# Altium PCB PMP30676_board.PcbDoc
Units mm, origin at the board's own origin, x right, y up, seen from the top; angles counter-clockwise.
Board outline 63.5 x 50.29 mm, 4 copper layers (Top Layer, GND, Signal Layer, Bottom Layer), stack 2.028 mm thick; 44 components, 21 nets, 103 pads, 77 vias.
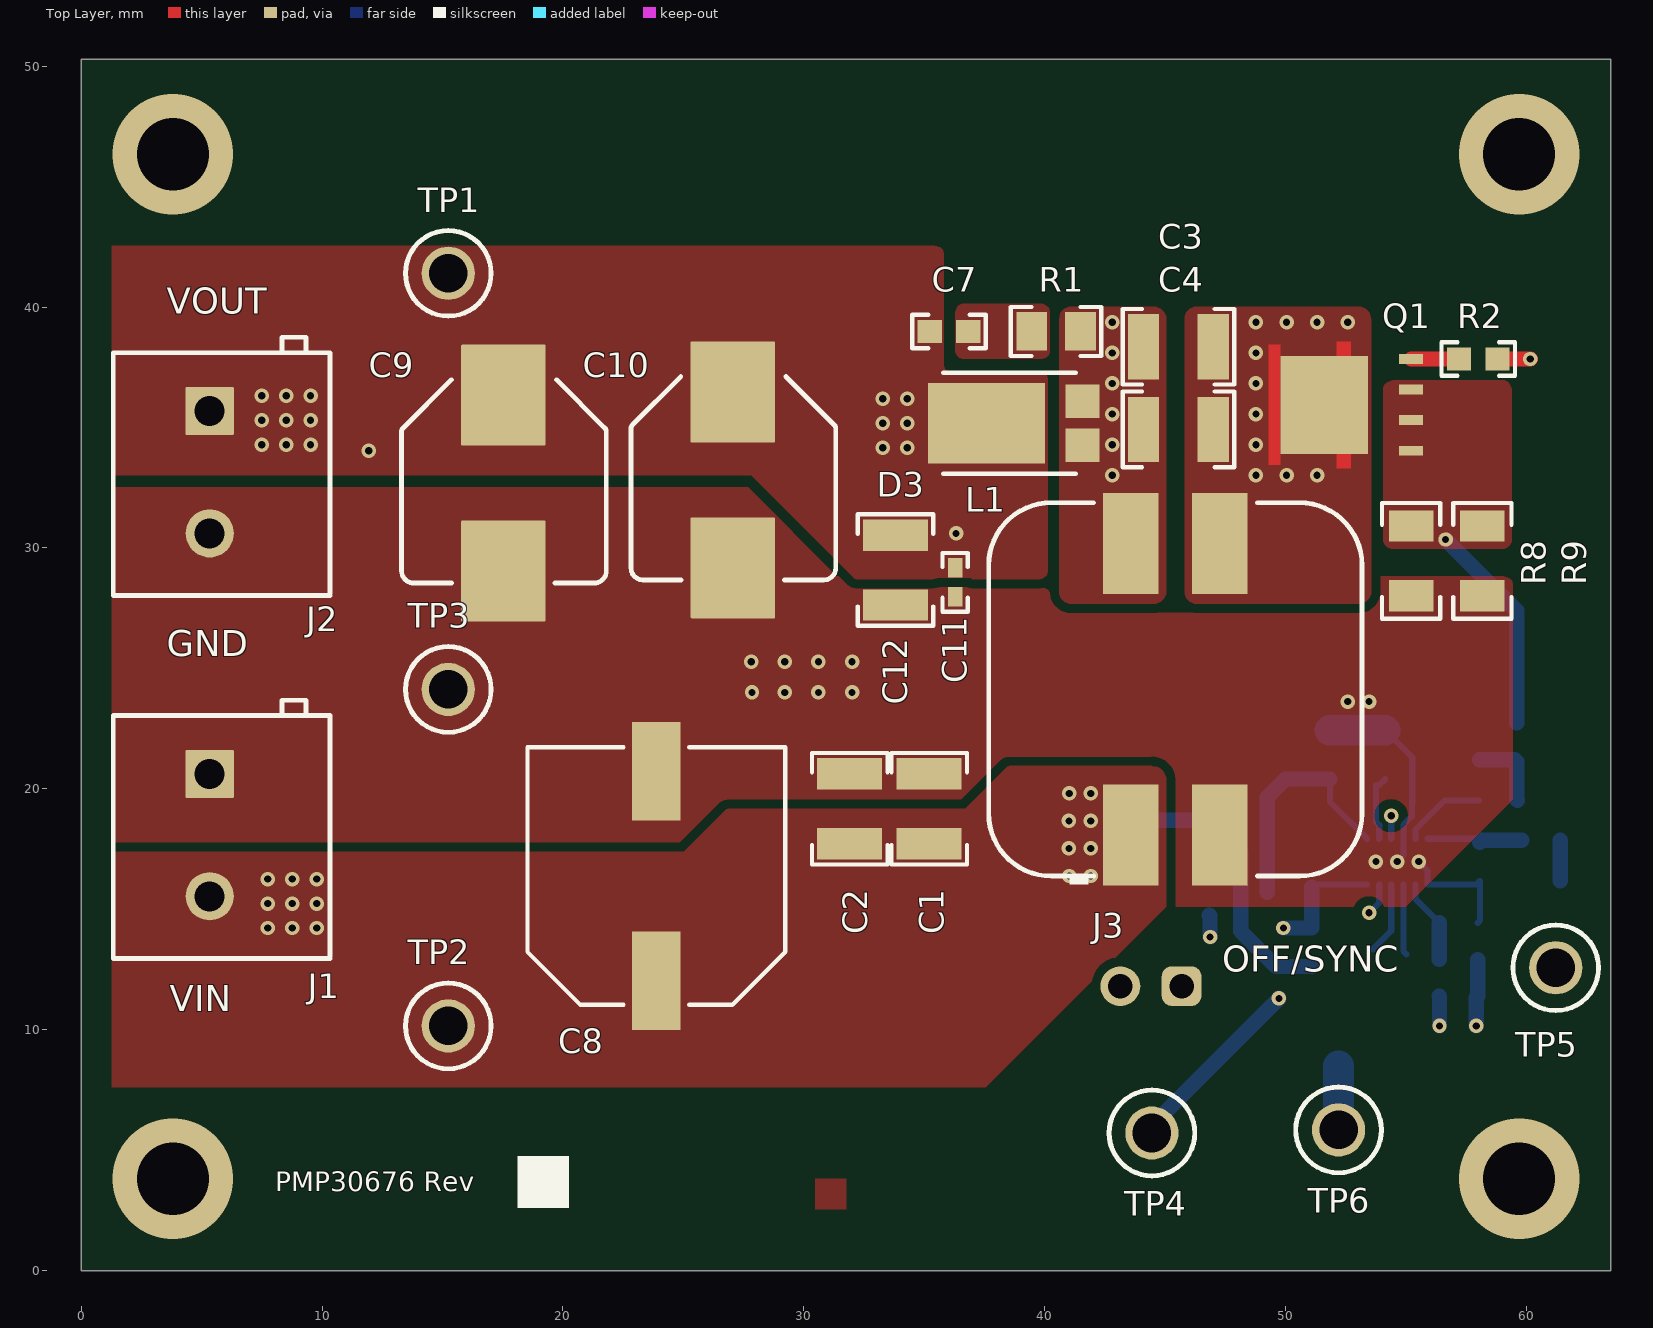
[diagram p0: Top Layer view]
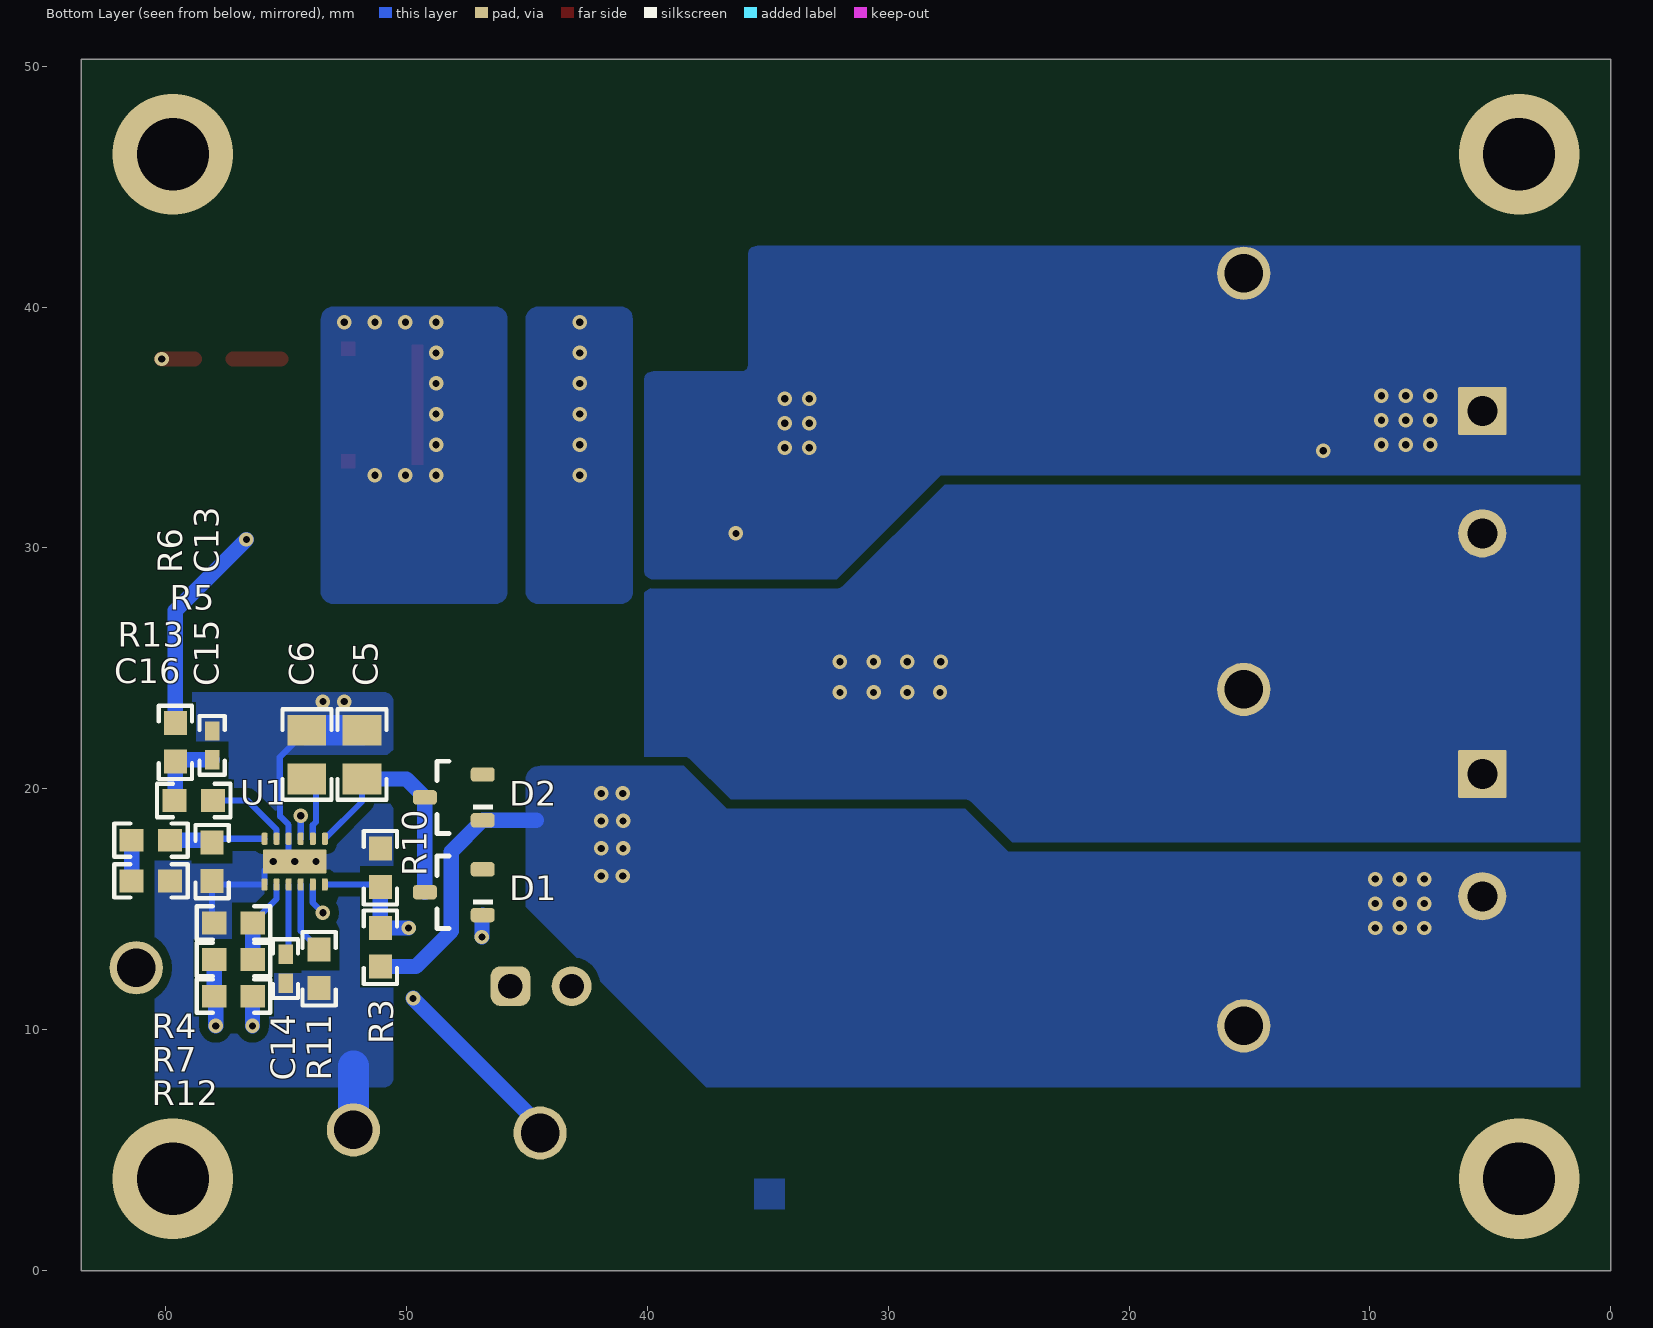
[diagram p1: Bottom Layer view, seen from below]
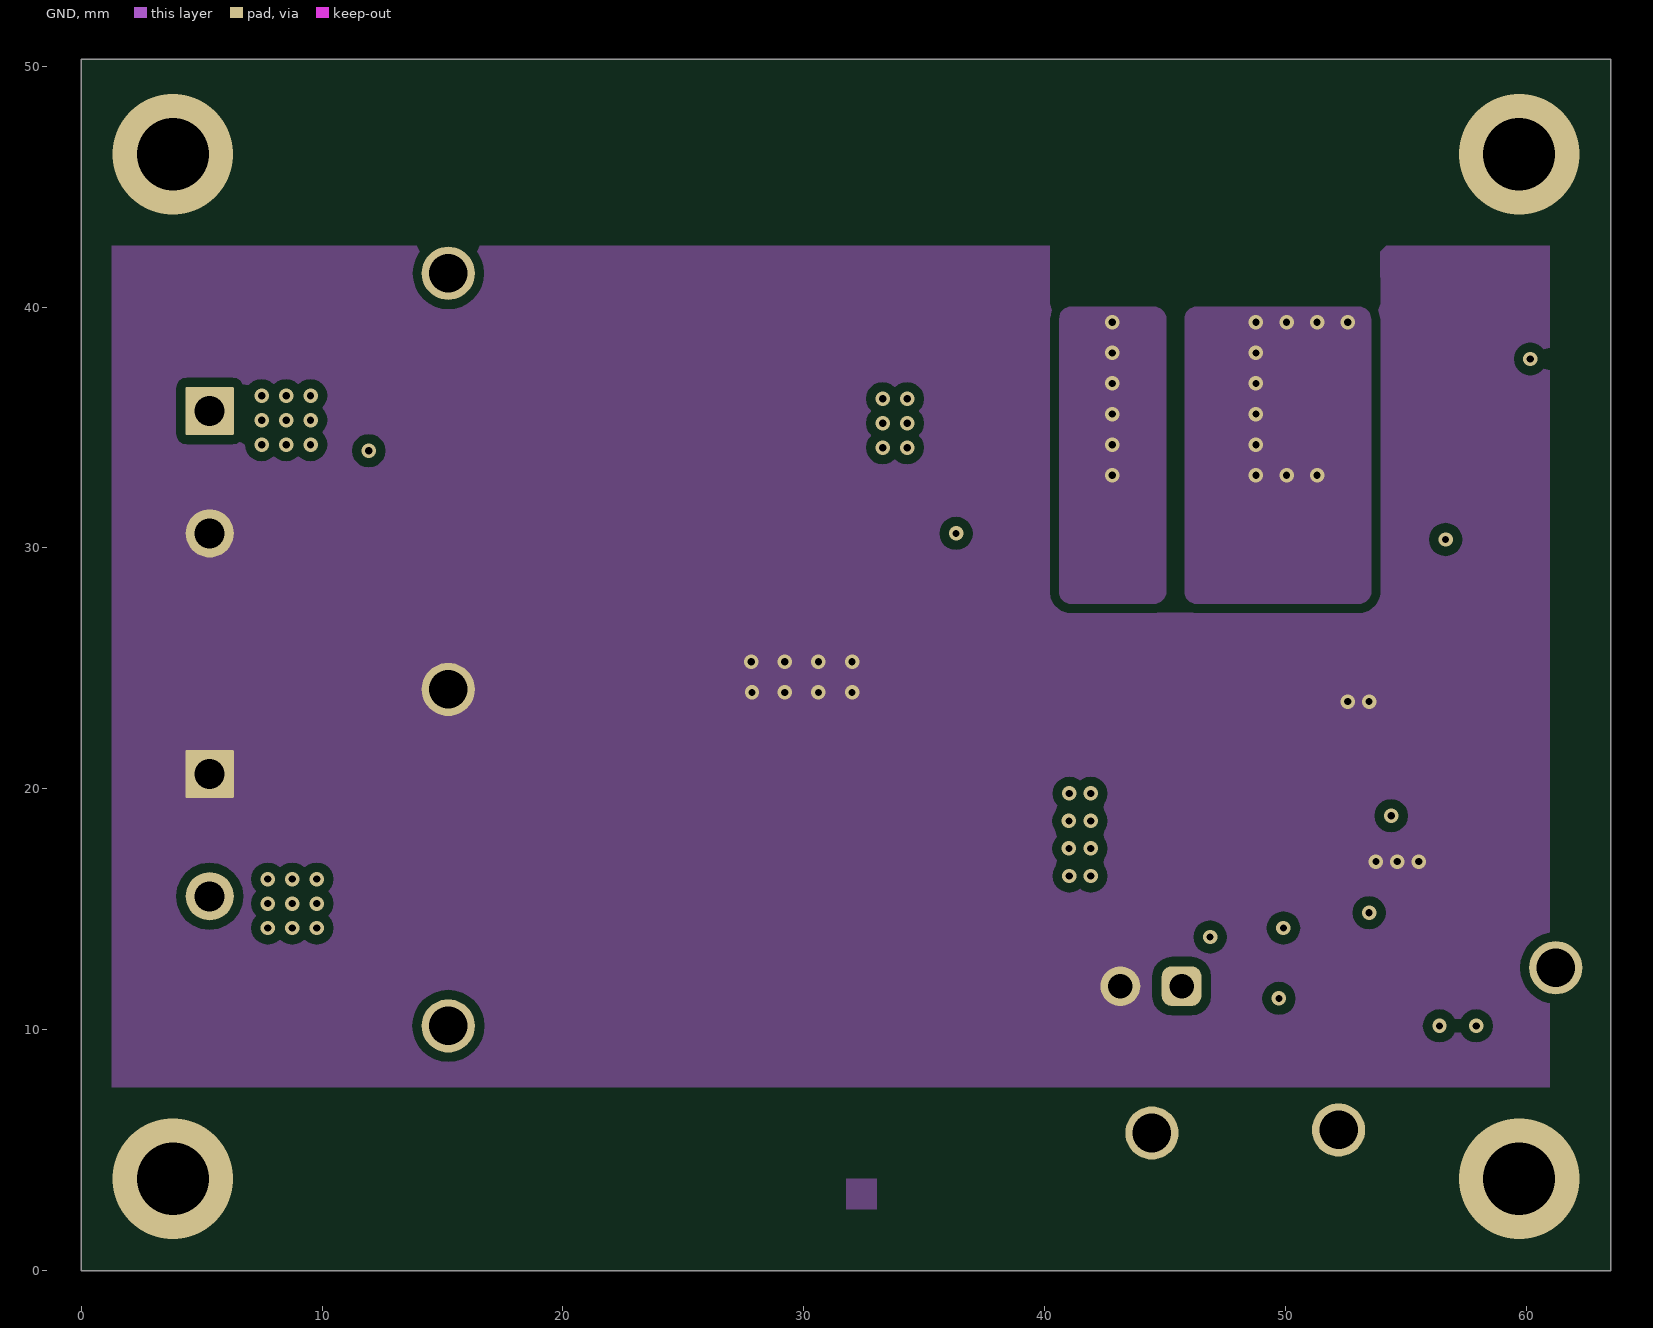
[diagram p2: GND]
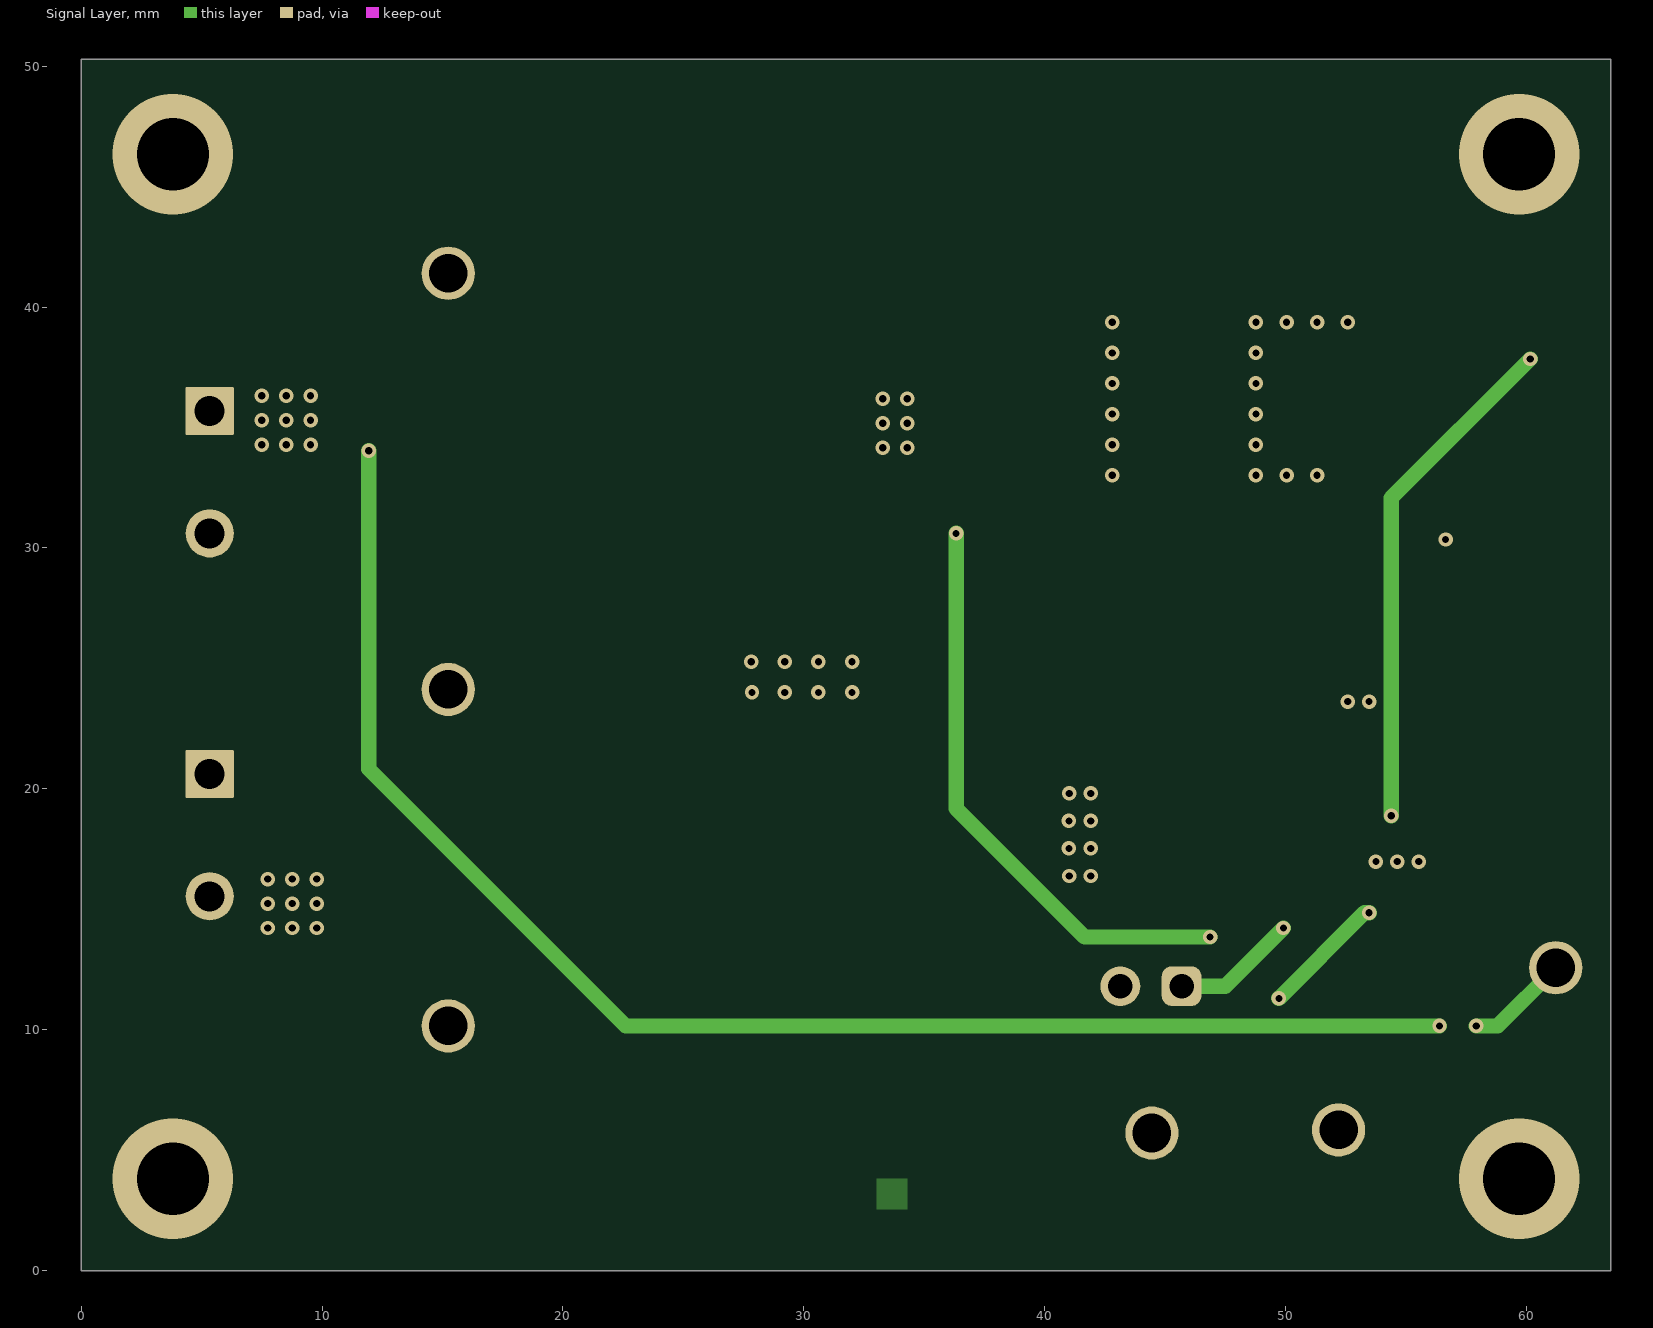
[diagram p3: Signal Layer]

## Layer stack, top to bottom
Top Solder: solder mask 0.0102, Solder Resist, Dk 3.5
Top Layer: signal copper 0.0356
Dielectric1: core 1.5037, FR-4, Dk 4.8
GND: signal copper 0.036
Dielectric 3: prepreg 0.127, Dk 4.2
Signal Layer: signal copper 0.036
Dielectric 2: core 0.254, Dk 4.2
Bottom Layer: signal copper 0.0356
Bottom Solder: solder mask 0.0102, Solder Resist, Dk 3.5

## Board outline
0,0 63.5,0 63.5,50.292 0,50.292

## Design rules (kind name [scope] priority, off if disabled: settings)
AcuteAngle [All] p1: minimum=4.50000000000000E+0001 checktracksonly=FALSE
AssemblyTestPointUsage [All] p1: valid=2
Clearance Clearance_Keepouts [((IsTrack Or IsArc) And Not InPoly) And IsFree and IsKeepOut vs ((IsTrack Or IsArc) And Not InPoly) And IsFree and IsKeepOut] p1: gap=0 ignorepadtopadclearanceinfootprint=FALSE
Clearance Clearance_BoardEdge_MountingHoles [OnCopper and InComponentClass('Mounting Holes') vs IsKeepOut] p2: gap=1.016 ignorepadtopadclearanceinfootprint=FALSE except(0: Arc-Hole Track-Hole SMDPad-Hole THPad-Hole Via-Hole Fill-Hole Poly-Hole Region-Hole Text-Hole)
Clearance Clearance_BoardEdge_Poly [OnCopper and InPoly vs IsKeepOut] p3: gap=0.635 ignorepadtopadclearanceinfootprint=FALSE except(0: Arc-Hole Track-Hole SMDPad-Hole THPad-Hole Via-Hole Fill-Hole Poly-Hole Region-Hole Text-Hole)
Clearance Clearance_BoardEdge [OnCopper and Not InComponentClass('Logo') and not InComponentClass('FiducialMark') and not InRegion(1000,500,4000,800) and Not IsKeepout vs IsKeepOut] p4: gap=1.905 ignorepadtopadclearanceinfootprint=FALSE except(0: Arc-Hole Track-Hole SMDPad-Hole THPad-Hole Via-Hole Fill-Hole Poly-Hole Region-Hole Text-Hole)
Clearance Clearance_Poly [InPolygon] p5: gap=0.381 ignorepadtopadclearanceinfootprint=FALSE except(0: Arc-Hole Track-Hole SMDPad-Hole THPad-Hole Via-Hole Fill-Hole Poly-Hole Region-Hole Text-Hole)
Clearance [All] p6: gap=0.2 ignorepadtopadclearanceinfootprint=FALSE except(0: Arc-Hole Track-Hole SMDPad-Hole THPad-Hole Via-Hole Fill-Hole Poly-Hole Region-Hole Text-Hole)
ComponentClearance ComponentClearance_MountingHoles_FiducialMarks [InComponentClass('Mounting Holes') vs InComponentClass('FiducialMark')] p1: gap=1.27 collisioncheckmode=3 verticalgap=0.254 showdistances=FALSE
ComponentClearance ComponentClearance_Shunt [InComponentClass('Header') vs InComponentClass('Shunt')] p2: gap=0 collisioncheckmode=3 verticalgap=0 showdistances=FALSE
ComponentClearance ComponentClearance_Logo [InComponentClass('Logo')] p3: gap=1.27 collisioncheckmode=3 verticalgap=0.254 showdistances=FALSE
ComponentClearance ComponentClearance_ScrewToNut [(HasFootprint('NY PMS 440 0025 PH')) vs (HasFootprint('Keystone_1902C'))] p4: gap=0.127 collisioncheckmode=3 verticalgap=0.254 showdistances=FALSE
ComponentClearance ComponentClearance_MountingHoles [InComponentClass('Mounting Holes')] p5: gap=6.35 collisioncheckmode=3 verticalgap=2540 showdistances=FALSE
ComponentClearance ComponentClearance_SmallPassives [HasFootprint('0201*') or HasFootprint('0402*') or HasFootprint('0508') or HasFootprint('0603*') or HasFootprint('0612') or HasFootprint('0805*') or HasFootprint('0815*') or HasFootprint('0830*') or HasFootprint('1206*') or HasFootprint('1210*') or HasFootprint('1808*') or HasFootprint('1812*') or HasFootprint('1825*') or HasFootprint('2010*') or HasFootprint('2220*') or HasFootprint('2225*') or HasFootprint('2512*') or HasFootprint('2728*') or HasFootprint('3518*') vs HasFootprint('0201*') or HasFootprint('0402*') or HasFootprint('0508') or HasFootprint('0603*') or HasFootprint('0612') or HasFootprint('0805*') or HasFootprint('0815*') or HasFootprint('0830*') or HasFootprint('1206*') or HasFootprint('1210*') or HasFootprint('1808*') or HasFootprint('1812*') or HasFootprint('1825*') or HasFootprint('2010*') or HasFootprint('2220*') or HasFootprint('2225*') or HasFootprint('2512*') or HasFootprint('2728*') or HasFootprint('3518*')] p6: gap=0.508 collisioncheckmode=3 verticalgap=0.254 showdistances=FALSE
ComponentClearance ComponentClearance_THtoSMT [IsThruComponent vs IsSMTComponent] p7: gap=2.54 collisioncheckmode=3 verticalgap=0.762 showdistances=FALSE
ComponentClearance ComponentClearance_THtoTH [IsThruComponent vs IsThruComponent] p8: gap=3 collisioncheckmode=3 verticalgap=0.762 showdistances=FALSE
ComponentClearance [All] p9: gap=1.016 collisioncheckmode=3 verticalgap=0.254 showdistances=FALSE
DiffPairsRouting [All] p1: maxlimit=2.54 minlimit=0.254 mostfreqgap=0.254 toplayer_minwidth=0.381 toplayer_maxwidth=0.381 toplayer_prefwidth=0.381 midlayer1_minwidth=0.381 midlayer1_maxwidth=0.381 midlayer1_prefwidth=0.381 midlayer2_minwidth=0.381 midlayer2_maxwidth=0.381 midlayer2_prefwidth=0.381 bottomlayer_minwidth=0.381 bottomlayer_maxwidth=0.381 bottomlayer_prefwidth=0.381 maxuncoupledlength=25.4
FabricationTestPointUsage TestPointUsage [All] p1: valid=2 allowmultiple=FALSE
FabricationTestpoint Testpoint [All] p1: side=3 testpointundercomponent=TRUE minsize=1.016 maxsize=2.54 preferedsize=1.524 minholesize=0 maxholesize=1.016 preferedholesize=0.813 testpointgrid=0.025 allowsidetop=TRUE allowsidebottom=TRUE usegrid=TRUE gridtolerance=0
FanoutControl Fanout_LCC [IsLCC] p1: bgadir=Out bgaviamode=Centered fanoutstyle=Auto fanoutdirection=Alternating viagrid=0.025 // Fanout_LCC (Default Rule)
FanoutControl Fanout_BGA [IsBGA] p2: bgadir=Out bgaviamode=Centered fanoutstyle=Auto fanoutdirection=Alternating viagrid=0.025 // Fanout_BGA (Default Rule)
FanoutControl Fanout_Default [All] p4: bgadir=Out bgaviamode=Centered fanoutstyle=Auto fanoutdirection=Alternating viagrid=0.025 // Fanout_Default (Default Rule)
FanoutControl Fanout_Small [(CompPinCount < 5)] p5: bgadir=Out bgaviamode=Centered fanoutstyle=Auto fanoutdirection=OutThenIn viagrid=0.025 // Fanout_Small (Default Rule)
HoleSize [All] p1: absolutevalues=TRUE maxlimit=6.375 minlimit=0.3 maxpercent=80.000 minpercent=20.000
MinimumAnnularRing MinimumAnnularRing_ThermalPadVias [IsVia and InAnyComponent] p1: minimumring=0.15
MinimumAnnularRing [All] p2: minimumring=0.15
MinimumSolderMaskSliver MinimumSolderMaskSliver_Logo [InComponentClass('Logo') vs InComponentClass('Logo')] p1: minsoldermaskwidth=0.018
MinimumSolderMaskSliver [All] p2: minsoldermaskwidth=0.1
PlaneConnect [All] p1: planeconnectstyle=Relief reliefexpansion=0.254 reliefentries=4 reliefconductorwidth=0.254 reliefairgap=0.254
PolygonConnect [All] p1: connectstyle=Direct reliefconductorwidth=0.254 reliefentries=4 polygonreliefangle="90 Angle" airgapwidth=0.254
RoutingVias ThermalPadVias [IsVia and InAnyComponent] p1: holewidth=0.2 width=0.5 viastyle="Through Hole" minholewidth=0.3 minwidth=0.6 maxholewidth=0.33 maxwidth=0.6
RoutingVias [All] p2: holewidth=0.3 width=0.6 viastyle="Through Hole" minholewidth=0.3 minwidth=0.6 maxholewidth=1.016 maxwidth=1.651
SilkToBoardRegionClearance [Not ((IsComment or IsDesignator) And (Hide <> 'False')) and not InRegion(1000,500,4000,800)] p1:
SilkToSilkClearance SilkToSilkClearance_Pb-FreeLogo [(HasFootprint('Pb-Free_Overlay_Medium') OR HasFootprint('Pb-Free_Overlay_Small')) vs (HasFootprint('Pb-Free_Overlay_Medium') OR HasFootprint('Pb-Free_Overlay_Small'))] p1: silktosilkclearance=0
SilkToSilkClearance [All] p2: silktosilkclearance=0.102
SilkToSolderMaskClearance SilkToComonentPadClearance [IsPad and InAnycomponent] p1: minsilkscreentomaskgap=0.127 clearancetoexposedcopper=TRUE
SilkToSolderMaskClearance "Silk to Solder Mask Opening" [All] p2: minsilkscreentomaskgap=0.102 clearancetoexposedcopper=FALSE
SolderMaskExpansion [All] p1: expansion=0.05
Width [All] p1: maxlimit=2.54 minlimit=0.152 preferedwidth=0.254 checkconnectedcopper=TRUE
15 further rules are at their usual default settings.

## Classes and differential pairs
component class Header: J3

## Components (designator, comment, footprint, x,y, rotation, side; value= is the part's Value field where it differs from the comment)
C1 "GRM32ER71H106KA12L" 1210_270 35.205,19.177 r90 top value=10uF
C2 "GRM32ER71H106KA12L" 1210_270 31.903,19.177 r90 top value=10uF
C3 "GRM32ER71H106KA12L" 1210_270 45.55,38.354 r0 top value=10uF
C4 "GRM32ER71H106KA12L" 1210_270 45.55,34.925 r0 top value=10uF
C5 "GRM21BR71H105KA12L" 0805_HV 51.842,21.425 r270 bottom value=1uF
C6 "GRM21BR71A105KA01L" 0805_HV 54.128,21.425 r90 bottom value=1uF
C7 "GRM188R71H102KA01D" 0603 36.025,38.989 r180 top value=1000pF
C8 "EEE-FC1H101P" SM_RADIAL_G 23.876,16.383 r90 top value=100uF
C9 "HHXC250ARA221MHA0G" HXB_HA0 17.526,33.147 r270 top value=220uF
C10 "HHXC250ARA221MHA0G" HXB_HA0 27.051,33.274 r270 top value=220uF
C11 "GRM155R71H104ME14D" 0402 36.279,28.575 r270 top value=0.1uF
C12 "GRM32DR71E106KA12L" 1210_220 33.808,29.083 r270 top value=10uF
C13 "GRM155R61E102KA01D" 0402 58.065,21.806 r90 bottom value=1000pF
C14 "GRM155R71C104KA88D" 0402 55.017,12.535 r270 bottom value=0.1uF
C15 "GRM188R71E332KA01D" 0603 58.065,16.98 r270 bottom value=3300pF
C16 "GRM188R71A334KA61D" 0603 60.605,16.18 r180 bottom value=0.33uF
D1 "BAS16LT1G" SOT-23 48.032,15.71 r0 bottom value=100V
D2 "BAS16LT1G" SOT-23 48.032,19.647 r0 bottom value=100V
D3 "PDS560-13" POWERDI5 39.581,35.179 r180 top value=60V
J1 "ED120/2DS" On-Shore_ED120_2DS 5.334,18.08 r270 top
J2 "ED120/2DS" On-Shore_ED120_2DS 5.334,33.147 r270 top
J3 "TSW-102-07-G-S" TSW-102-07-G-S 44.412,11.811 r180 top
L1 "MSD1514-223MEB" MSD1514 45.423,24.13 r90 top value=22uH
Q1 "SQJA60EP" PowerPAK_SO-8L 52.408,35.941 r180 top value=60V
R1 "CRCW08051R00FKEA" 0805_HV 40.47,38.989 r0 top value=1.00
R2 "ERJ-3GEY0R00V" 0603 57.996,37.846 r180 top value=0
R3 "CRCW0603261KFKEA" 0603 51.08,13.424 r270 bottom value=261k
R4 "CRCW060349R9FKEA" 0603 57.176,11.392 r180 bottom value=49.9
R5 "ERJ-3GEY0R00V" 0603 58.827,19.52 r0 bottom value=0
R6 "CRCW0603100RFKEA" 0603 59.589,21.933 r90 bottom value=100
R7 "CRCW060360K4FKEA" 0603 57.176,12.916 r0 bottom value=60.4k
R8 "CSR1206FK15L0" 1206 55.213,29.464 r90 top value=0.015
R9 "CSR1206FK15L0" 1206 58.166,29.464 r90 top value=0.015
R10 "CRCW060386K6FKEA" 0603 51.08,16.726 r270 bottom value=86.6k
R11 "CRCW060371K5FKEA" 0603 53.62,12.535 r90 bottom value=71.5k
R12 "CRCW06035K49FKEA" 0603 57.176,14.44 r180 bottom value=5.49k
R13 "CRCW06036K49FKEA" 0603 60.605,17.869 r180 bottom value=6.49k
TP1 "5010" Keystone5010 15.24,41.402 r0 top
TP2 "5010" Keystone5010 15.24,10.16 r0 top
TP3 "5011" Keystone5011 15.24,24.13 r0 top
TP4 "5012" Keystone5012 44.45,5.715 r0 top
TP5 "5014" Keystone5014 61.214,12.573 r0 top
TP6 "5011" Keystone5011 52.197,5.842 r0 top
U1 "LM51551QDSSRQ1" DSS0012C 54.636,16.98 r270 bottom

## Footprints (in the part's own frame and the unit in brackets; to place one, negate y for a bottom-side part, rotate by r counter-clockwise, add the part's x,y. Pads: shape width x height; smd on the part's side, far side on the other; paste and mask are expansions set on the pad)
0402 [mm] "0402 from SM-752 data"
  rect 0.8x0.6 smd: 1(-0.6,0) 2(0.6,0)
  silkscreen extent -1.22,-0.52 1.22,0.52, body extent -0.55,-0.3 0.55,0.3, height 0.6
0603 [mm] "0603 from SM-752 data"
  rect 1x0.95 smd: 1(-0.8,0) 2(0.8,0)
  silkscreen extent -1.52,-0.69 1.52,0.69, body extent -0.87,-0.47 0.87,0.47, height 1
0805_HV [mil] "0805 with 30mil clearance between pads"
  rect 50x63 smd: 1(-40,0) 2(40,0)
  silkscreen extent -74,-40 74,40, body extent -43,-29 43,29, height 57
1206 [mm] "1206 from SM-752 data"
  rect 1.3x1.85 smd: 1(-1.45,0) 2(1.45,0)
  silkscreen extent -2.4,-1.21 2.4,1.21, body extent -1.7,-0.9 1.7,0.9, height 1.35
1210_220 [mm] "1210"
  rect 1.3x2.7 smd: 1(-1.45,0) 2(1.45,0)
  silkscreen extent -2.32,-1.57 2.32,1.57, body extent -1.7,-1.35 1.7,1.35, height 2.2
1210_270 [mm] "1210"
  rect 1.3x2.7 smd: 1(-1.45,0) 2(1.45,0)
  silkscreen extent -2.32,-1.57 2.32,1.57, body extent -1.7,-1.35 1.7,1.35, height 2.7
DSS0012C [mm] "WSON-12"
  rrect40% 0.5x0.25 smd: 1(-0.95,1.25) 2(-0.95,0.75) 3(-0.95,0.25) 4(-0.95,-0.25) 5(-0.95,-0.75) 6(-0.95,-1.25) 7(0.95,-1.25) 8(0.95,-0.75) 9(0.95,-0.25) 10(0.95,0.25) 11(0.95,0.75) 12(0.95,1.25)
  rrect11% 0.95x1.17 on Bottom Paste: 13(0,-0.685) 13(0,0.685)
  rrect11% 1x2.65 smd paste-0.5: 13(0,0)
  body extent -1,-1.5 1,1.5, height 0.81
HXB_HA0 [mm] "SMD, 2-Leads, Dia 8mm"
  rrect3% 4.2x3.5 smd: 1(-3.2,0) 2(4.1,0)
  silkscreen extent -3.84,-4.23 4.6,4.28, body extent -4.22,-4.2 4.98,4.3, height 10.5
Keystone5010 [mil] "Keystone Multipurpose loops"
  round 87 hole 63: 1(0,0)
  silkscreen extent -70,-70 70,70, body extent -63,-63 63,62, height 319
Keystone5011 [mil] "Keystone Multipurpose loops"
  round 87 hole 63: 1(0,0)
  silkscreen extent -70,-70 70,70, body extent -63,-63 63,62, height 319
Keystone5012 [mil] "Keystone Multipurpose loops"
  round 87 hole 63: 1(0,0)
  silkscreen extent -70,-70 70,70, body extent -63,-63 63,62, height 319
Keystone5014 [mil] "Keystone Multipurpose loops"
  round 87 hole 63: 1(0,0)
  silkscreen extent -70,-70 70,70, body extent -63,-63 63,62, height 319
MSD1514 [mm] "SMD, 4-Leads, Body 15x15mm"
  rect 4.2x2.3 smd: 1(-6.05,1.85) 2(-6.05,-1.85) 3(6.05,-1.85) 4(6.05,1.85)
  silkscreen extent -8.1,-7.75 7.75,7.75, body extent -7.81,-7.75 7.79,7.75, height 14.2
On-Shore_ED120_2DS [mm] "ONSHORE"
  rrect5% 2x2 hole 1.25: 1(-2.54,0)
  round 2 hole 1.25: 2(2.54,0)
  silkscreen extent -5.6,-4 5.12,5, body extent -5.78,-4 5.08,5, height 13
POWERDI5 [mm] "Diodes Inc recommended land pattern, ap02001.pdf rev 60"
  rect 1.4x1.39 smd: 1(-1.991,0.92) 2(-1.991,-0.92)
  rect 4.86x3.36 smd: 3(1.991,0)
  silkscreen extent -1.7,-2.1 3.8,2.1, body extent -2.27,-2.03 4.33,2.03, height 1.17
PowerPAK_SO-8L [mm] "based on Vishay recommended land pattern Document 63818 Feb 7, 2012"
  rect 1x0.41 smd: 1(-2.805,1.905) 2(-2.805,0.635) 3(-2.805,-0.635) 4(-2.805,-1.905)
  rect 3.63x4.061 smd: 5(0.805,0)
  Top Layer region: 2.615,-2.5 3.125,-2.5 3.125,2.5 2.615,2.5
  Top Layer region: -0.298,2.03 0.297,2.03 0.297,2.64 -0.298,2.64
  Top Layer region: -0.298,-2.64 0.298,-2.64 0.298,-2.03 -0.298,-2.03
  body extent -3.07,-2.57 3.08,2.57, height 1.21
SM_RADIAL_G [mm] "10 x 10.2mm:  Panasonic G"
  rect 4.1x2 smd: 1(-4.35,0) 2(4.35,0)
  silkscreen extent -5.35,-5.35 5.35,5.35, body extent -5.25,-5.25 5.25,5.25, height 10.5
SOT-23 [mm] "SOT23, 3-Leads, Body 2.9x1.3mm, Pitch 0.95mm, Lead Span 2.5mm, IPC Medium Density"
  rrect50% 1x0.6 smd: 1(-1.2,0.95) 2(-1.2,-0.95) 3(1.2,0)
  silkscreen extent -1.63,-1.5 0.7,1.5, body extent -1.16,-1.45 1.21,1.45, height 1
TSW-102-07-G-S [mm] "Samtec 100mil, 1x2, 230 mil above insulator"
  rrect50% 1.65x1.65 hole 1.016: 1(-1.27,0)
  round 1.65 hole 1.016: 2(1.27,0)
  body extent -2.54,-1.27 2.54,1.27, height 8.38

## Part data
C1 C2 C3 C4: library part CMP-0009226-3, "CAP, CERM, 10 uF, 50 V, +/- 10%, X7R, 1210", Cap_Case=1210, Manufacturer=MuRata, Supplier Part Number 1=490-6544-1-ND, TempCo=X7R, Tolerance_%=10%, Value1=Unknown, Value2=50V, ValueDisplayed=10uF
C5: library part CMP-0008350-2, "CAP, CERM, 1 uF, 50 V, +/- 10%, X7R, 0805", Cap_Case=0805, Manufacturer=MuRata, Supplier Part Number 1=490-4736-1-ND, TempCo=X7R, Tolerance_%=10%, Value1=Unknown, Value2=50V, ValueDisplayed=1uF
C6: library part CMP-0008313-2, "CAP, CERM, 1 uF, 10 V, +/- 10%, X7R, 0805", Cap_Case=0805, Manufacturer=MuRata, Supplier Part Number 1=490-1695-1-ND, TempCo=X7R, Tolerance_%=10%, Value1="0.007 ohm", Value2=10V, ValueDisplayed=1uF
C7: library part CMP-0007432-3, "CAP, CERM, 1000 pF, 50 V, +/- 10%, X7R, 0603", Cap_Case=0603, Manufacturer=MuRata, Supplier Part Number 1=490-1494-1-ND, TempCo=X7R, Tolerance_%=10%, Value1=Unknown, Value2=50V, ValueDisplayed=1000pF
C8: library part CMP-0011166-2, "CAP, AL, 100 uF, 50 V, +/- 20%, 0.3 ohm, SMD", Cap_Case=G, Manufacturer=Panasonic, Supplier Part Number 1=PCE4013CT-ND, Tolerance_%=20%, Value1="0.3 ohm", Value2=50V, ValueDisplayed=100uF
C9 C10: library part CMP-0012270-3, "CAP, Aluminum Polymer, 220 uF, 25 V, +/- 20%, 0.027 ohm, AEC-Q200 Grade 2, D8xL10mm SMD", Cap_Case=HA0, Manufacturer=Chemi-Con, Tolerance_%=20%, Value1="0.027 ohm", Value2=25V, ValueDisplayed=220uF
C11: library part CMP-0006675-2, "CAP, CERM, 0.1 uF, 50 V, +/- 20%, X7R, 0402", Cap_Case=0402, Manufacturer=MuRata, Supplier Part Number 1=490-10701-1-ND, TempCo=X7R, Tolerance_%=20%, Value1=Unknown, Value2=50V, ValueDisplayed=0.1uF
C12: library part CMP-0009190-2, "CAP, CERM, 10 uF, 25 V, +/- 10%, X7R, 1210", Cap_Case=1210, Manufacturer=MuRata, Supplier Part Number 1=490-1867-1-ND, TempCo=X7R, Tolerance_%=10%, Value1=Unknown, Value2=25V, ValueDisplayed=10uF
C13: library part CMP-0006606-2, "CAP, CERM, 1000 pF, 25 V, +/- 10%, X5R, 0402", Cap_Case=0402, Manufacturer=MuRata, Supplier Part Number 1=GRM155R61E102KA01D-ND, TempCo=X5R, Tolerance_%=10%, Value1=Unknown, Value2=25V, ValueDisplayed=1000pF
C14: library part CMP-0006641-2, "CAP, CERM, 0.1 uF, 16 V, +/- 10%, X7R, 0402", Cap_Case=0402, Manufacturer=MuRata, Supplier Part Number 1=490-3261-1-ND, TempCo=X7R, Tolerance_%=10%, Value1=Unknown, Value2=16V, ValueDisplayed=0.1uF
C15: library part CMP-0007418-4, "CAP, CERM, 3300 pF, 25 V, +/- 10%, X7R, 0603", Cap_Case=0603, Manufacturer=MuRata, Supplier Part Number 1=GRM188R71E332KA01D-ND, TempCo=X7R, Tolerance_%=10%, Value1=Unknown, Value2=25V, ValueDisplayed=3300pF
C16: library part CMP-0007371-4, "CAP, CERM, 0.33 uF, 10 V, +/- 10%, X7R, 0603", Cap_Case=0603, Manufacturer=MuRata, Supplier Part Number 1=GRM188R71A334KA61D-ND, TempCo=X7R, Tolerance_%=10%, Value1=Unknown, Value2=10V, ValueDisplayed=0.33uF
D1 D2: library part CMP-0029193-2, "Diode, Switching, 100 V, 0.2 A, SOT-23", Manufacturer="ON Semiconductor", Value1=0.2A, Value2=1.25V
D3: library part CMP-0028523-2, "Diode, Schottky, 60 V, 5 A, PowerDI5", Manufacturer="Diodes Inc.", Value1=5A, Value2=0.67V
J1 J2: library part CMP-0074910-1, "Terminal Block, 5.08 mm, 2x1, Brass, TH", Color=Blue, Current_A=15A, Manufacturer="On-Shore Technology", Supplier Part Number 1=ED1609-ND, Voltage_V=300V
J3: library part CMP-0075405-2, "Header, 100mil, 2x1, Gold, TH", Color=Black, Current_A=6.3A, Manufacturer=Samtec, Supplier Part Number 1=SAM1029-02-ND, Voltage_V=550V
L1: library part CMP-0080785-1, "Coupled inductor, 22 µH, 11 A, 0.031 ohm, SMD", Manufacturer=Coilcraft, ValueDisplayed=22µH
Q1: library part CMP-0000880-1, "MOSFET, N-CH, 60 V, 30 A, AEC-Q101, PowerPAK_SO-8L", Alternate Manufacturer=None, Manufacturer=Vishay-Siliconix, Value1=0.01, Value2="18 nC"
R1: library part CMP-0021009-2, "RES, 1.00, 1%, 0.125 W, 0805", Manufacturer=Vishay-Dale, Power_W=125mW, Supplier Part Number 1=72M6849, TempCo="100 ppm/C", Tolerance_%=1%, Value2=0.125W, Value_Code=1R00, ValueDisplayed=DNP
R2 R5: library part CMP-0025874-4, "RES, 0, 5%, 0.1 W, AEC-Q200 Grade 0, 0603", Manufacturer=Panasonic, Power_W=100mW, Supplier Part Number 1=P0.0GCT-ND, TempCo="600 ppm/C", Tolerance_%=5%, Value2=0.1W, Value_Code=0000, ValueDisplayed=0
R3: library part CMP-0022244-4, "RES, 261 k, 1%, 0.1 W, AEC-Q200 Grade 0, 0603", Manufacturer=Vishay-Dale, Power_W=100mW, Supplier Part Number 1=541-261KHCT-ND, TempCo="100 ppm/C", Tolerance_%=1%, Value2=0.1W, Value_Code=261k
R4: library part CMP-0022448-4, "RES, 49.9, 1%, 0.1 W, AEC-Q200 Grade 0, 0603", Manufacturer=Vishay-Dale, Power_W=100mW, Supplier Part Number 1=541-49.9HCT-ND, TempCo="100 ppm/C", Tolerance_%=1%, Value2=0.1W, Value_Code=49R9, ValueDisplayed=49.9
R6: library part CMP-0021991-2, "RES, 100, 1%, 0.1 W, 0603", Manufacturer=Vishay-Dale, Power_W=100mW, Supplier Part Number 1=541-100HCT-ND, TempCo="100 ppm/C", Tolerance_%=1%, Value2=0.1W, Value_Code=100R, ValueDisplayed=100
R7: library part CMP-0022532-4, "RES, 60.4 k, 1%, 0.1 W, AEC-Q200 Grade 0, 0603", Manufacturer=Vishay-Dale, Power_W=100mW, Supplier Part Number 1=541-60.4KHCT-ND, TempCo="100 ppm/C", Tolerance_%=1%, Value2=0.1W, Value_Code=60k4, ValueDisplayed=60.4k
R8 R9: library part CMP-0017258-2, "RES, 0.015, 1%, 0.5 W, 1206", Manufacturer="Stackpole Electronics Inc", Power_W=500mW, Supplier Part Number 1=CSR1206FK15L0CT-ND, TempCo="100 ppm/C", Tolerance_%=1%, Value2=0.5W, Value_Code=R015, ValueDisplayed=0.015
R10: library part CMP-0022628-4, "RES, 86.6 k, 1%, 0.1 W, AEC-Q200 Grade 0, 0603", Manufacturer=Vishay-Dale, Power_W=100mW, Supplier Part Number 1=541-86.6KHCT-ND, TempCo="100 ppm/C", Tolerance_%=1%, Value2=0.1W, Value_Code=86k6, ValueDisplayed=86.6k
R11: library part CMP-0022581-4, "RES, 71.5 k, 1%, 0.1 W, AEC-Q200 Grade 0, 0603", Manufacturer=Vishay-Dale, Power_W=100mW, Supplier Part Number 1=541-71.5KHCT-ND, TempCo="100 ppm/C", Tolerance_%=1%, Value2=0.1W, Value_Code=71k5, ValueDisplayed=71.5k
R12: library part CMP-0022512-4, "RES, 5.49 k, 1%, 0.1 W, AEC-Q200 Grade 0, 0603", Manufacturer=Vishay-Dale, Power_W=100mW, Supplier Part Number 1=541-5.49KHCT-ND, TempCo="100 ppm/C", Tolerance_%=1%, Value2=0.1W, Value_Code=5k49, ValueDisplayed=5.49k
R13: library part CMP-0022561-4, "RES, 6.49 k, 1%, 0.1 W, AEC-Q200 Grade 0, 0603", Manufacturer=Vishay-Dale, Power_W=100mW, Supplier Part Number 1=541-6.49KHCT-ND, TempCo="100 ppm/C", Tolerance_%=1%, Value2=0.1W, Value_Code=6k49, ValueDisplayed=6.49k
TP1 TP2: library part CMP-0055147-1, "Test Point, Multipurpose, Red, TH", Color=Red, Manufacturer=Keystone, Supplier Part Number 1=36-5010-ND
TP3 TP6: library part CMP-0055148-1, "Test Point, Multipurpose, Black, TH", Color=Black, Manufacturer=Keystone, Supplier Part Number 1=36-5011-ND
TP4: library part CMP-0055149-1, "Test Point, Multipurpose, White, TH", Color=White, Manufacturer=Keystone, Supplier Part Number 1=36-5012-ND
TP5: library part CMP-0055151-1, "Test Point, Multipurpose, Yellow, TH", Color=Yellow, Manufacturer=Keystone, Supplier Part Number 1=36-5014-ND
U1: library part CMP-0081541-1, "Automotive Grade 2.2-MHz Wide Input Non-synchronous Boost Controller, DSS0012C (WSON-12)", Alternate Manufacturer="Texas Instruments", Alternate PartNumber=LM51551QDSSTQ1

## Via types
v1: diameter 0.6, hole 0.3, Top Layer to Bottom Layer, 71 vias
v2: diameter 5, hole 3, Top Layer to Bottom Layer, 4 vias
v3: diameter 0.6, hole 0.3, Top Layer to Bottom Layer, tented both sides, 2 vias

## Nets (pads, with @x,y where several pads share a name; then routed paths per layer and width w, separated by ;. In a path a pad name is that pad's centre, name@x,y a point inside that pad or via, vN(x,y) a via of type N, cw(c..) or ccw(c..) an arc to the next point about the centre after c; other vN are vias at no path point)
GND: C1.2 C2.2 C5.1 C6.2 C8.2 C9.2 C10.2 C11.2 C12.2 C13.2 C14.2 C15.2 C16.2 J1.1 J2.2 J3.2 L1.2 R8.1 R9.1 R10.1 R11.1 R12.1 TP3.1 TP6.1 U1.4 U1.7 U1.13@54.636,16.98 | length 15.7
  Bottom Layer w0.254: C6.2 55.255,21.314 55.255,19.403 55.245,19.392 55.245,18.861 54.886,18.502 U1.4 54.886,17.23 v1(54.636,16.98) ; v1(55.525,16.98) 55.886,16.619 U1.7 57.915,16.03 C15.2 58.065,14.529 R12.1
  Bottom Layer w1.27: C5.1 C6.2 ; TP6.1@52.197,6.35 52.197,8.509
  other v1: 53.747,16.98 27.848,24.003 29.21,24.003 30.607,24.003 32.004,24.003 27.813,25.273 29.21,25.273 30.607,25.273 32.004,25.273
  other v3: 52.578,23.622 53.467,23.622
NetC3_1: C3.1 C4.1 D3.1 D3.2 L1.4 R1.2
  other v1: 42.799,33.02 42.799,34.29 42.799,35.56 42.799,36.83 42.799,38.1 42.799,39.37
NetC3_2: C3.2 C4.2 L1.3 Q1.5
  other v1: 48.768,33.02 50.038,33.02 51.308,33.02 48.768,34.29 48.768,35.56 48.768,36.83 48.768,38.1 48.768,39.37 50.038,39.37 51.308,39.37 52.578,39.37
NetC5_2: C5.2 D1.3 D2.3 U1.1 | length 10
  Bottom Layer w0.254: C5.2 51.842,19.474 U1.1
  Bottom Layer w0.635: D1.3 D2.3 49.994,20.409 C5.2
NetC6_1: C6.1 U1.2 | length 2.8
  Bottom Layer w0.254: U1.2 53.886,18.494 53.755,18.625 53.755,20.167 53.886,20.167 C6.1
NetC7_1: C7.1 R1.1
NetC13_1: C13.1 R5.2 R6.1 | length 3.2
  Bottom Layer w0.635: C13.1 59.516,21.206 R6.1 59.589,19.558 R5.2
NetC14_1: C14.1 U1.9 | length 2.9
  Bottom Layer w0.254: U1.9 54.886,13.266 C14.1
NetC15_1: C15.1 R13.2 U1.6 | length 4
  Bottom Layer w0.254: U1.6 57.915,17.93 C15.1
  Bottom Layer w0.635: C15.1 58.154,17.869 R13.2
NetC16_1: C16.1 R13.1 | length 1.7
  Bottom Layer w0.635: C16.1 R13.1
NetJ3_1: J3.1 R3.1 R10.2 U1.12 | length 10.9
  Signal Layer w0.635: J3.1@45.212,11.811 47.498,11.811 v1(49.911,14.224)
  Bottom Layer w0.254: R10.2 51.184,16.03 U1.12
  Bottom Layer w0.635: v1(49.911,14.224) R3.1 R10.2
NetQ1_1: Q1.1 Q1.2 Q1.3 R6.2 R8.2 R9.2 | length 8.8
  Bottom Layer w0.635: v1(56.642,30.353) 59.589,27.406 R6.2
NetQ1_4: Q1.4 R2.2 | length 2
  Top Layer w0.635: Q1.4 R2.2
NetR2_1: R2.1 U1.3 | length 23.7
  Top Layer w0.635: R2.1 v1(60.155,37.846)
  Signal Layer w0.635: v1(54.382,18.885) 54.382,32.073 v1(60.155,37.846)
  Bottom Layer w0.254: v1(54.382,18.885) 54.386,18.881 U1.3
NetR4_1: R4.1 R7.2 TP5.1 | length 7.1
  Signal Layer w0.635: v1(57.912,10.16) 58.801,10.16 TP5.1
  Bottom Layer w0.635: v1(57.912,10.16) 57.912,11.328 R4.1 R7.2
NetR5_1: R5.1 U1.5 | length 3.5
  Bottom Layer w0.254: U1.5 55.386,18.302 56.604,19.52 R5.1
NetR11_2: R11.2 U1.10 | length 3
  Bottom Layer w0.254: R11.2 54.386,14.101 U1.10
NetTP4_1: TP4.1 U1.11 | length 14.3
  Signal Layer w0.635: v1(49.721,11.303) 53.276,14.859 v1(53.467,14.859)
  Bottom Layer w0.254: v1(53.467,14.859) 53.886,15.278 U1.11
  Bottom Layer w0.635: TP4.1 44.45,6.033 v1(49.721,11.303)
VFB: R7.1 R12.2 U1.8 | length 3.5
  Bottom Layer w0.254: U1.8 55.386,15.43 R12.2
  Bottom Layer w0.635: R7.1 R12.2
VIN: C1.1 C2.1 C8.1 D2.1 J1.2 L1.1 R3.2 TP2.1 | length 10.9
  Bottom Layer w0.635: 44.605,18.697 D2.1 48.133,17.396 48.133,14.097 49.606,12.624 R3.2
  other v1: 7.747,14.224 8.763,14.224 9.779,14.224 7.747,15.24 8.763,15.24 9.779,15.24 7.747,16.256 8.763,16.256 9.779,16.256 41.021,16.383 41.91,16.383 41.002,17.526 41.91,17.526 41.004,18.669 41.91,18.669 41.021,19.812 41.91,19.812
VOUT: C7.2 C9.1 C10.1 C11.1 C12.1 D1.1 D3.3 J2.1 R4.2 TP1.1 | length 88.4
  Signal Layer w0.635: v1(11.938,34.036) 11.938,20.828 22.606,10.16 v1(56.388,10.16) ; v1(36.322,30.607) 36.322,19.185 41.656,13.851 v1(46.863,13.851)
  Bottom Layer w0.635: D1.1 46.863,14.729 v1(46.863,13.851) ; R4.2 56.388,11.38 v1(56.388,10.16)
  other v1: 33.274,34.163 34.29,34.163 7.493,34.29 8.509,34.29 9.525,34.29 33.274,35.179 34.29,35.179 7.493,35.306 8.509,35.306 9.525,35.306 33.274,36.195 34.29,36.195 7.493,36.322 8.509,36.322 9.525,36.322
pads on no net: D1.2 D2.2 U1.13@53.951,16.98 U1.13@55.321,16.98
copper on no net:
  other v2: 3.81,3.81 59.69,3.81 3.81,46.35 59.69,46.35

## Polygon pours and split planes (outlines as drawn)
NetC3_2 on Bottom Layer "NETC3_2_L04_P110" (solid, remove dead copper, pour order 110): 46.312,27.686 cw(c46.312,28.194) 45.804,28.194 45.804,39.497 cw(c46.312,39.497) 46.312,40.005 53.043,40.005 cw(c53.043,39.497) 53.551,39.497 53.551,28.194 cw(c53.043,28.194) 53.043,27.686
NetC3_1 on Bottom Layer "NETC3_1_L04_P108" (solid, remove dead copper, pour order 108): 44.534,27.686 ccw(c44.534,28.194) 45.042,28.194 45.042,39.497 ccw(c44.534,39.497) 44.534,40.005 41.102,40.005 ccw(c41.102,39.5) 40.597,39.5 40.597,28.194 ccw(c41.105,28.194) 41.105,27.686
GND on Bottom Layer "GND_L04_P104" (solid, remove dead copper, pour order 104): 40.132,15.382 40.132,29.098 31.369,29.098 27.693,32.773 1.27,32.773 1.27,15.382
no net on Bottom Layer "NONET_L04_P102" (solid, remove dead copper, pour order 102): 1.27,17.78
VOUT on Bottom Layer "VOUT_L04_P100" (solid, remove dead copper, pour order 100): 40.132,29.083 40.132,36.957 ccw(c39.751,36.957) 39.751,37.338 36.068,37.338 cw(c36.068,37.592) 35.814,37.592 35.814,42.164 ccw(c35.433,42.164) 35.433,42.545 1.27,42.545 1.27,33.02 27.813,33.02 32.131,28.702 39.751,28.702 ccw(c39.751,29.083)
VIN on Bottom Layer "VIN_L04_P088" (solid, remove dead copper, pour order 88): 45.042,20.363 ccw(c44.45,20.363) 44.45,20.955 38.481,20.955 36.703,19.177 26.797,19.177 25.019,17.399 21.971,17.399 1.27,17.399 1.27,7.62 37.549,7.62 45.042,15.113
GND on Bottom Layer "GND_L04_P096" (solid, remove dead copper, pour order 96): 50.546,23.622 cw(c50.927,23.622) 50.927,24.003 60.071,24.003 cw(c60.071,23.622) 60.452,23.622 60.452,8.001 cw(c60.071,8.001) 60.071,7.62 50.927,7.62 cw(c50.927,8.001) 50.546,8.001
no net on Bottom Layer "NONET_L04_P072" (solid, pour order 72): 34.29,2.54 34.29,3.81 35.56,3.81 35.56,2.54
VIN on Top Layer "VIN_L01_P098" (solid, remove dead copper, pour order 98): 45.042,20.363 ccw(c44.45,20.363) 44.45,20.955 38.481,20.955 36.703,19.177 26.797,19.177 25.019,17.399 21.971,17.399 1.27,17.399 1.27,7.62 37.549,7.62 45.042,15.113
GND on Top Layer "GND_L01_P094" (solid, remove dead copper, pour order 94): 54.991,15.113 59.436,19.558 59.436,28.448 ccw(c59.055,28.448) 59.055,28.829 31.369,28.829 27.686,32.512 1.27,32.512 1.27,15.113
VOUT on Top Layer "VOUT_L01_P092" (solid, remove dead copper, pour order 92): 40.132,29.083 40.132,36.957 ccw(c39.751,36.957) 39.751,37.338 36.068,37.338 cw(c36.068,37.592) 35.814,37.592 35.814,42.164 ccw(c35.433,42.164) 35.433,42.545 1.27,42.545 1.27,33.02 27.813,33.02 32.131,28.702 39.751,28.702 ccw(c39.751,29.083)
NetC7_1 on Top Layer "NETC7_1_L01_P086" (solid, remove dead copper, pour order 86): 39.835,37.846 ccw(c39.835,38.227) 40.216,38.227 40.216,39.751 ccw(c39.835,39.751) 39.835,40.132 36.626,40.132 ccw(c36.626,39.785) 36.279,39.785 36.279,38.227 ccw(c36.66,38.227) 36.66,37.846
NetC3_1 on Top Layer "NETC3_1_L01_P084" (solid, remove dead copper, pour order 84): 44.534,27.686 ccw(c44.534,28.194) 45.042,28.194 45.042,39.497 ccw(c44.534,39.497) 44.534,40.005 41.102,40.005 ccw(c41.102,39.5) 40.597,39.5 40.597,28.194 ccw(c41.105,28.194) 41.105,27.686
NetC3_2 on Top Layer "NETC3_2_L01_P082" (solid, remove dead copper, pour order 82): 46.312,27.686 cw(c46.312,28.194) 45.804,28.194 45.804,39.497 cw(c46.312,39.497) 46.312,40.005 53.043,40.005 cw(c53.043,39.497) 53.551,39.497 53.551,28.194 cw(c53.043,28.194) 53.043,27.686
NetQ1_1 on Top Layer "NETQ1_1_L01_P080" (solid, remove dead copper, pour order 80): 54.44,29.972 cw(c54.44,30.353) 54.059,30.353 54.059,36.576 cw(c54.44,36.576) 54.44,36.957 58.25,36.957 59.012,36.957 cw(c59.012,36.576) 59.393,36.576 59.393,30.353 cw(c59.012,30.353) 59.012,29.972
no net on Top Layer "NONET_L01_P078" (solid, pour order 78): 30.48,2.54 30.48,3.81 31.75,3.81 31.75,2.54
no net on Signal Layer "NONET_L03_P074" (solid, pour order 74): 33.02,3.81 34.29,3.81 34.29,2.54 33.02,2.54
NetC3_2 on GND "NETC3_2_L02_P114" (solid, remove dead copper, pour order 114): 46.312,27.686 cw(c46.312,28.194) 45.804,28.194 45.804,39.497 cw(c46.312,39.497) 46.312,40.005 53.043,40.005 cw(c53.043,39.497) 53.551,39.497 53.551,28.194 cw(c53.043,28.194) 53.043,27.686
NetC3_1 on GND "NETC3_1_L02_P112" (solid, remove dead copper, pour order 112): 44.534,27.686 ccw(c44.534,28.194) 45.042,28.194 45.042,39.497 ccw(c44.534,39.497) 44.534,40.005 41.102,40.005 ccw(c41.102,39.5) 40.597,39.5 40.597,28.194 ccw(c41.105,28.194) 41.105,27.686
GND on GND "GND_L02_P116" (solid, remove dead copper, pour order 116): 1.27,42.545 1.27,7.62 60.96,7.62 60.96,42.545
no net on GND "NONET_L02_P076" (solid, pour order 76): 31.75,2.54 31.75,3.81 33.02,3.81 33.02,2.54
no net on Top Overlay "NONET_L-01_P-001" (solid): 18.117,2.619 18.117,4.747 20.244,4.747 20.244,2.619

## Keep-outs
Keep-Out Layer:
  text ".Layer_Name" at 14.656,-21.806 h1.52

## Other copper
Top Layer:
  pour cut-out: 44.576,27.559 44.576,27.305 46.228,27.305 46.228,27.559
  text ".Layer_Name" at 14.656,-21.806 h1.52
GND:
  pour cut-out: 44.576,27.559 44.576,27.305 46.228,27.305 46.228,27.559
  pour cut-out: 40.209,42.545 40.209,40.132 53.94,40.132 53.93,42.535 53.94,42.545
Bottom Layer:
  text ".Layer_Name" at 14.656,-21.806 h1.52

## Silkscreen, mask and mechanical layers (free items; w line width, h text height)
Top Overlay:
  text "VOUT" at 3.556,39.37 h1.85
  text "GND" at 3.556,25.146 h1.85
  text "OFF/SYNC" at 47.371,12.065 h1.85
  text "VIN" at 3.683,10.414 h1.85
  text "PMP30676 Rev" at 8.052,3.302 h0.8
  text ".Layer_Name" at 14.656,-21.806 h1.52
Bottom Overlay:
  text ".Layer_Name" at 14.656,-21.806 h1.52
Top Paste:
  text ".Layer_Name" at 14.656,-21.806 h1.52
Bottom Paste:
  text ".Layer_Name" at 14.656,-21.806 h1.52
Top Solder:
  text ".Layer_Name" at 14.656,-21.806 h1.52
  text ".Layer_Name" at 14.656,-21.806 h1.52
Bottom Solder:
  text ".Layer_Name" at 14.656,-21.806 h1.52
Drill Guide:
  text ".Layer_Name" at 14.656,-21.806 h1.52
M1 Board Outline:
  lines w0.3: 132.207,0 132.334,0.127
  lines w0.5: 0,0 0,50.292 63.5,50.292 63.5,0 0,0
  text ".Layer_Name" at 14.656,-21.806 h1.52
M2 Board Dimensions:
  rectangle: 3.175,-10.16 12.7,-6.985
  rectangle: 0,-6.985 3.175,-3.81
  lines w0.178: 0,-6.985 25.4,-6.985 ; 3.175,-10.16 3.175,-3.81 ; 6.35,-10.16 6.35,-3.81 ; 12.7,-10.16 12.7,-3.81 ; 19.05,-10.16 19.05,-3.81 ; 0,-10.16 0,-3.81 25.4,-3.81 25.4,-10.16 0,-10.16
  text "PMP30676" at 0,52.705 h1.85
  text ".Layer_Name" at 14.656,-21.806 h1.52
M3 3D STEP Top:
  text ".Layer_Name" at 14.656,-21.806 h1.52
M4 3D STEP Bottom:
  text ".Layer_Name" at 14.656,-21.806 h1.52
M5 Assembly Top:
  lines w0.254: -7.417,-23.626 160.223,-23.626 ; -7.417,-18.462 160.274,-18.462 ; -7.417,-13.297 -7.417,-28.791 94.31,-28.791 160.274,-28.791 160.274,-13.297 -7.404,-13.297 -7.404,-28.791 32.614,-28.791 ; 55.194,-28.791 55.194,-13.297 ; 87.376,-18.462 87.376,-13.297 ; 108.712,-18.462 108.712,-13.297 ; 124.511,-28.956 124.511,-23.804
  text "COMPONENTS MARKED 'DNP' SHOULD NOT BE POPULATED." at 29.299,-8.09 h1.52
  text "ASSEMBLY VARIANT:" at 29.286,-11.024 h1.52
  text ".VariantName" at 55.601,-11.024 h1.52
  text "PCB VIEWED FROM TOP SIDE" at -5.804,-16.654 h1.52
  text "BOARD #:" at 57.099,-16.654 h1.52
  text ".PRJ_Number" at 70.955,-16.654 h1.52
  text "REV:" at 92.405,-16.654 h1.52
  text ".PCB_Rev" at 99.809,-16.654 h1.52
  text "SVN REV:" at 113.69,-16.654 h1.52
  text ".VersionControl_RevNumber" at 126.543,-16.654 h1.52
  text "TID #:" at 57.099,-21.819 h1.52
  text ".TID" at 70.955,-21.819 h1.52
  text "PLOT NAME =" at -5.804,-27.034 h1.52
  text ".plot_File_Name" at 14.656,-27.034 h1.52
  text "GENERATED    :" at 57.15,-27.034 h1.52
  text ".Print_Date" at 79.235,-27.034 h1.52
  text ".Print_Time" at 97.752,-27.034 h1.52
  text "TEXAS INSTRUMENTS" at 129.87,-27.034 h1.52
M6 Assembly Bottom:
  lines w0.254: -7.429,-18.474 160.261,-18.474 ; -7.379,-23.639 160.261,-23.639 ; 28.334,-28.969 28.334,-23.817 ; 44.133,-18.474 44.133,-13.31 ; 65.468,-18.474 65.468,-13.31 ; 97.65,-28.804 97.65,-13.31 ; 120.231,-28.804 160.249,-28.804 160.249,-13.31 -7.429,-13.31 -7.429,-28.804 58.534,-28.804 160.261,-28.804 160.261,-13.31
  text "COMPONENTS MARKED 'DNP' SHOULD NOT BE POPULATED." at 154.991,-8.077 h1.52
  text ".VariantName" at 128.473,-11.024 h1.52
  text "ASSEMBLY VARIANT:" at 154.864,-11.024 h1.52
  text ".VersionControl_RevNumber" at 26.302,-16.667 h1.52
  text "SVN REV:" at 39.154,-16.667 h1.52
  text ".PCB_Rev" at 53.035,-16.667 h1.52
  text "REV:" at 60.439,-16.667 h1.52
  text ".PRJ_Number" at 81.89,-16.667 h1.52
  text "BOARD #:" at 95.745,-16.667 h1.52
  text "PCB VIEWED FROM BOTTOM SIDE" at 158.648,-16.667 h1.52
  text ".TID" at 81.89,-21.831 h1.52
  text "TID #:" at 95.745,-21.831 h1.52
  text "TEXAS INSTRUMENTS" at 22.974,-27.047 h1.52
  text ".Print_Time" at 55.093,-27.047 h1.52
  text ".Print_Date" at 73.609,-27.047 h1.52
  text "GENERATED    :" at 95.694,-27.047 h1.52
  text ".plot_File_Name" at 138.189,-27.047 h1.52
  text "PLOT NAME =" at 158.648,-27.047 h1.52
M9 Title Sheet:
  drawing of 57 lines, arcs and shapes, not listed
  text "1" at 18.792,204.127 h1.78
  text "2" at 82.182,204.127 h1.78
  text "3" at 145.411,204.127 h1.78
  text "4" at 209.08,204.127 h1.78
  text "5" at 272.555,204.127 h1.78
  text "6" at 336.182,204.127 h1.78
  text "A" at -10.579,175.095 h1.78
  text "A" at 365.341,175.095 h1.78
  text "B" at -10.579,114.643 h1.78
  text "B" at 365.341,114.643 h1.78
  text "C" at -10.579,54.318 h1.78
  text "C" at 365.341,54.318 h1.78
  text "PROJECT TITLE:" at 288.125,7.048 h1.14
  text ".PRJ_Title" at 289.395,3.662 h1.78
  text "DESIGNED FOR:" at 288.125,-0.597 h1.14
  text ".PRJ_Customer" at 289.395,-4.153 h1.78
  text "D" at -10.579,-5.88 h1.78
  text "D" at 365.341,-5.88 h1.78
  text "FILE NAME:" at 288.125,-8.217 h1.14
  text ".PCB_File_Name_No_Path" at 289.395,-11.265 h1.78
  text "Texas Instruments (TI) and/or its licensors do not warrant the accuracy or completeness of this specification" at 161.9,-15.376 h1.14
  text "ENGINEER:" at 288.125,-15.583 h1.14
  text "LAYOUT BY:" at 326.352,-15.583 h1.14
  text "or any information contained therein. TI and/or its licensors do not warrant that this design will meet" at 160.757,-18.237 h1.14
  text ".PRJ_Engineer" at 289.395,-19.52 h1.78
  text ".PCB_Layout" at 327.635,-19.52 h1.78
  text "the specifications, will be suitable for your application or fit for any particular purpose, or will operate in" at 160.757,-21.099 h1.14
  text ".Layer_Name" at 14.656,-21.806 h1.52
  text "ALTIUM DESIGNER VERSION:" at 326.352,-23.457 h1.14
  text "an implementation. TI and/or its licensors do not warrant that the design is production worthy. You should" at 160.757,-23.961 h1.14
  text "completely validate and test your design implementation to confirm the system functionality for your application." at 161.9,-26.822 h1.14
  text ".print_Scale" at 289.395,-26.843 h1.78
  text ".Application_BuildNumber" at 327.635,-26.843 h1.78
  text "1" at 18.792,-32.093 h1.78
  text "2" at 82.182,-32.093 h1.78
  text "3" at 145.411,-32.093 h1.78
  text "4" at 209.08,-32.093 h1.78
  text "5" at 272.555,-32.093 h1.78
  text "6" at 336.182,-32.093 h1.78
M10 Fab Notes:
  drawing of 173 lines, arcs and shapes, not listed
  text "DESIGN INFORMATION" at 314.376,157.505 h1.52
  text "MIN. TRACK WIDTH:" at 298.004,152.933 h1.52
  text "8" at 325.849,152.933 h1.52
  text "MIL" at 329.78,152.933 h1.52
  text "MIN. CLEARANCE:" at 298.004,149.581 h1.52
  text "0.2" at 324.325,149.581 h1.52
  text "mm" at 329.78,149.581 h1.52
  text "MIN. VIA PAD SIZE:" at 298.004,146.228 h1.52
  text "24" at 325.087,146.228 h1.52
  text "MIL" at 329.78,146.228 h1.52
  text "0.05mm (2MIL)" at 315.657,142.628 h1.52
  text "MINIMUM ANNULAR RING" at 289.642,142.52 h1.52
  text "EXTERNAL" at 333.641,142.52 h1.52
  text "PER" at 294.722,139.522 h1.52
  text "IPC-D-275 CLASS 2 LEVEL C" at 300.31,139.522 h1.52
  text "MIL, HOLES" at 338.111,136.67 h1.52
  text "+/-" at 328.143,136.652 h1.52
  text "+/-" at 349.834,136.652 h1.52
  text "REGISTRATION TOLERANCES:" at 289.642,136.525 h1.52
  text "METAL" at 320.116,136.525 h1.52
  text "5" at 334.752,136.525 h1.52
  text "3" at 355.91,136.525 h1.52
  text "MIL" at 358.863,136.525 h1.52
  text "+/-" at 349.834,133.655 h1.52
  text "HOLE SIZE TOLERANCE (UNLESS OTHERWISE SPECIFIED):" at 289.642,133.528 h1.52
  text "3" at 355.91,133.528 h1.52
  text "MIL" at 358.863,133.528 h1.52
  text "MATERIAL:" at 287.743,128.208 h1.52
  text "FR-4 High Tg" at 312.799,124.643 h1.52
  text "FR-408" at 298.436,124.425 h1.52
  text "OTHER" at 336.231,124.425 h1.52
  text "X" at 308.864,124.333 h1.52
  text "62 MIL (1.6mm) +/-10%" at 306.567,120.292 h1.52
  text "THICKNESS:" at 289.642,120.184 h1.52
  text "X" at 303.311,120.184 h1.52
  text "OTHER" at 339.203,120.184 h1.52
  text "TOLERANCE:" at 289.642,116.17 h1.52
  text "X" at 310.96,116.17 h1.52
  text "ANSI IPC-6012 TYPE 3 CLASS 2" at 315.709,116.17 h1.52
  text "OTHER +/-" at 315.708,112.208 h1.52
  text "BOW & TWIST:" at 289.642,108.22 h1.52
  text "X" at 310.96,108.22 h1.52
  text "ANSI IPC-6012 TYPE 3 CLASS 2" at 315.709,108.22 h1.52
  text "OTHER +/-" at 315.708,104.194 h1.52
  text "DRILLING:" at 287.743,100.676 h1.52
  text "REFERENCE:" at 289.642,97.705 h1.52
  text "X" at 306.107,97.705 h1.52
  text "AS SHOWN" at 310.857,97.705 h1.52
  text "X" at 328.992,97.705 h1.52
  text "NC_DRILL FILES" at 332.472,97.705 h1.52
  text "PTH COPPER THICKNESS:" at 289.642,93.691 h1.52
  text "X" at 318.35,93.691 h1.52
  text "20-30 um" at 321.83,93.691 h1.52
  text "OTHER" at 340.041,93.691 h1.52
  text "BOARD FINISH:" at 287.743,89.653 h1.52
  text "SILKSCREEN:" at 291.685,86.656 h1.52
  text "X" at 315.784,86.656 h1.52
  text "TOP" at 318.985,86.656 h1.52
  text "X" at 328.738,86.656 h1.52
  text "BOTTOM" at 331.964,86.656 h1.52
  text "SILKSCREEN COLOR:" at 291.685,82.414 h1.52
  text "X" at 315.758,82.414 h1.52
  text "WHITE" at 318.985,82.414 h1.52
  text "OTHER" at 331.964,82.414 h1.52
  text "X" at 319.086,78.37 h1.52
  text "GREEN" at 322.312,78.37 h1.52
  text "OTHER" at 338.009,78.37 h1.52
  text "SOLDER RESIST COLOR:" at 291.685,78.096 h1.52
  text "X" at 319.086,74.052 h1.52
  text "MATTE" at 322.312,74.052 h1.52
  text "SEMI-GLOSS" at 337.998,74.036 h1.52
  text "IMMERSION GOLD (ENIG)" at 314.692,69.264 h1.52
  text "ENEPIG" at 348.666,69.18 h1.52
  text "SURFACE FINISH:" at 287.743,69.155 h1.52
  text "X" at 309.944,69.155 h1.52
  text "IMM. TIN/SILVER OR EQUIV" at 296.113,65.167 h1.52
  text "OTHER" at 332.472,65.167 h1.52
  text "ARRAY/PANEL:" at 287.743,60.621 h1.52
  text "CUT AND TRIM PER M1 BOARD OUTLINE" at 314.692,60.512 h1.52
  text "N.C. ROUTE" at 314.692,56.658 h1.52
  text "X" at 331.939,56.658 h1.52
  text "V. SCORE" at 336.689,56.658 h1.52
  text "CERTIFICATION:" at 287.743,53.178 h1.52
  text "MATERIALS AND WORKMANSHIP FOR ALL PCBS" at 306.158,53.178 h1.52
  text "TO MEET OR EXCEED THE REQUIREMENTS OF:" at 306.158,50.689 h1.52
  text "X" at 296.671,47.222 h1.52
  text "ANSI IPC-A-600F CLASS ->" at 300.202,47.222 h1.52
  text "X" at 341.834,47.222 h1.52
  text "2" at 344.855,47.222 h1.52
  text "1" at 336.854,47.184 h1.52
  text "3" at 353.846,47.184 h1.52
  text "X" at 317.348,43.171 h1.52
  text "RoHS" at 320.826,43.171 h1.52
  text "OTHER" at 337.194,43.171 h1.52
  text "PER ORDER" at 347.28,43.171 h1.52
  text "ALL BOARDS MUST MEET OR EXCEED UL94-V0 REQUIREMENTS." at 288.442,38.964 h1.52
  text "PCB MUST BEAR THE UL94V-0 UL REGISTERED MATERIAL ID NUMBER" at 288.442,35.916 h1.52
  text "ADDITIONAL REQUIREMENTS:" at 287.743,31.512 h1.52
  text "MICROSECTION:" at 289.642,28.591 h1.52
  text "YES" at 312.648,28.591 h1.52
  text "REQUIRED" at 334.53,24.625 h1.52
  text "BARE BOARD ELEC. TEST:" at 289.642,24.553 h1.52
  text "NONE" at 322.808,24.553 h1.52
  text "X" at 331.304,24.553 h1.52
  text "PER ORDER" at 349.566,24.553 h1.52
  text ".Layer_Name" at 14.656,-21.806 h1.52
M11 Gerber Information:
  lines w0.254: -7.417,-23.626 160.223,-23.626 ; -7.417,-18.462 160.274,-18.462 ; -7.417,-13.297 -7.417,-28.791 94.31,-28.791 160.274,-28.791 160.274,-13.297 -7.404,-13.297 -7.404,-28.791 32.614,-28.791 ; 55.194,-28.791 55.194,-13.297 ; 87.376,-18.462 87.376,-13.297 ; 108.712,-18.462 108.712,-13.297 ; 124.511,-28.956 124.511,-23.804
  text "ALL ARTWORK VIEWED FROM TOP SIDE" at -5.804,-16.654 h1.52
  text "BOARD #:" at 57.099,-16.654 h1.52
  text ".PRJ_Number" at 70.955,-16.654 h1.52
  text "REV:" at 92.405,-16.654 h1.52
  text ".PCB_Rev" at 99.809,-16.654 h1.52
  text "SVN REV:" at 113.69,-16.654 h1.52
  text ".VersionControl_RevNumber" at 126.543,-16.654 h1.52
  text "LAYER NAME =" at -5.804,-21.806 h1.52
  text "TID #:" at 57.099,-21.819 h1.52
  text ".TID" at 70.955,-21.819 h1.52
  text "PLOT NAME =" at -5.804,-27.034 h1.52
  text ".plot_File_Name" at 14.656,-27.034 h1.52
  text "GENERATED    :" at 57.15,-27.034 h1.52
  text ".Print_Date" at 79.235,-27.034 h1.52
  text ".Print_Time" at 97.752,-27.034 h1.52
  text "TEXAS INSTRUMENTS" at 129.87,-27.034 h1.52
M12 Stackup:
  drawing of 295 lines, arcs and shapes, not listed
  text "Layer" at 248.871,194.881 h1.52
  text "Name" at 259.283,194.881 h1.52
  text "Material" at 282.898,194.881 h1.52
  text "Thickness" at 304.736,194.881 h1.52
  text "Constant" at 321.242,194.881 h1.52
  text "Board Layer Stack" at 335.717,194.881 h1.52
  text "1" at 248.871,191.833 h1.52
  text "Top Overlay" at 259.283,191.833 h1.52
  text "2" at 248.871,188.785 h1.52
  text "Top Solder" at 259.283,188.785 h1.52
  text "Solder Resist" at 282.898,188.785 h1.52
  text "0.40mil" at 304.736,188.785 h1.52
  text "3.5" at 321.242,188.785 h1.52
  text "3" at 248.871,185.737 h1.52
  text "Top Layer" at 259.283,185.737 h1.52
  text "Copper" at 282.898,185.737 h1.52
  text "1.40mil" at 304.736,185.737 h1.52
  text "4" at 248.871,182.689 h1.52
  text "Dielectric1" at 259.283,182.689 h1.52
  text "FR-4" at 282.898,182.689 h1.52
  text "59.20mil" at 304.736,182.689 h1.52
  text "4.8" at 321.242,182.689 h1.52
  text "5" at 248.871,179.641 h1.52
  text "GND" at 259.283,179.641 h1.52
  text "Copper" at 282.898,179.641 h1.52
  text "1.42mil" at 304.736,179.641 h1.52
  text "6" at 248.871,176.594 h1.52
  text "Dielectric 3" at 259.283,176.594 h1.52
  text "5.00mil" at 304.736,176.594 h1.52
  text "4.2" at 321.242,176.594 h1.52
  text "7" at 248.871,173.546 h1.52
  text "Signal Layer" at 259.283,173.546 h1.52
  text "Copper" at 282.898,173.546 h1.52
  text "1.42mil" at 304.736,173.546 h1.52
  text "8" at 248.871,170.498 h1.52
  text "Dielectric 2" at 259.283,170.498 h1.52
  text "10.00mil" at 304.736,170.498 h1.52
  text "4.2" at 321.242,170.498 h1.52
  text "9" at 248.871,167.45 h1.52
  text "Bottom Layer" at 259.283,167.45 h1.52
  text "Copper" at 282.898,167.45 h1.52
  text "1.40mil" at 304.736,167.45 h1.52
  text "10" at 248.871,164.401 h1.52
  text "Bottom Solder" at 259.283,164.401 h1.52
  text "Solder Resist" at 282.898,164.401 h1.52
  text "0.40mil" at 304.736,164.401 h1.52
  text "3.5" at 321.242,164.401 h1.52
  text "11" at 248.871,161.353 h1.52
  text "Bottom Overlay" at 259.283,161.353 h1.52
  text ".Layer_Name" at 14.656,-21.806 h1.52
M13 Component Bodies Top:
  text ".Layer_Name" at 14.656,-21.806 h1.52
M14 Component Bodies Bottom:
  text ".Layer_Name" at 14.656,-21.806 h1.52
M15 Courtyards Top:
  text ".Layer_Name" at 14.656,-21.806 h1.52
M16 Courtyards Bottom:
  text ".Layer_Name" at 14.656,-21.806 h1.52
Drill Drawing:
  text ".Layer_Name" at 14.656,-21.806 h1.52

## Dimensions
0,0 to 63.5,0 on M2 Board Dimensions
0,-10.16 to 25.4,-10.16 on M2 Board Dimensions
0,0 to -3.302,50.165 on M2 Board Dimensions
